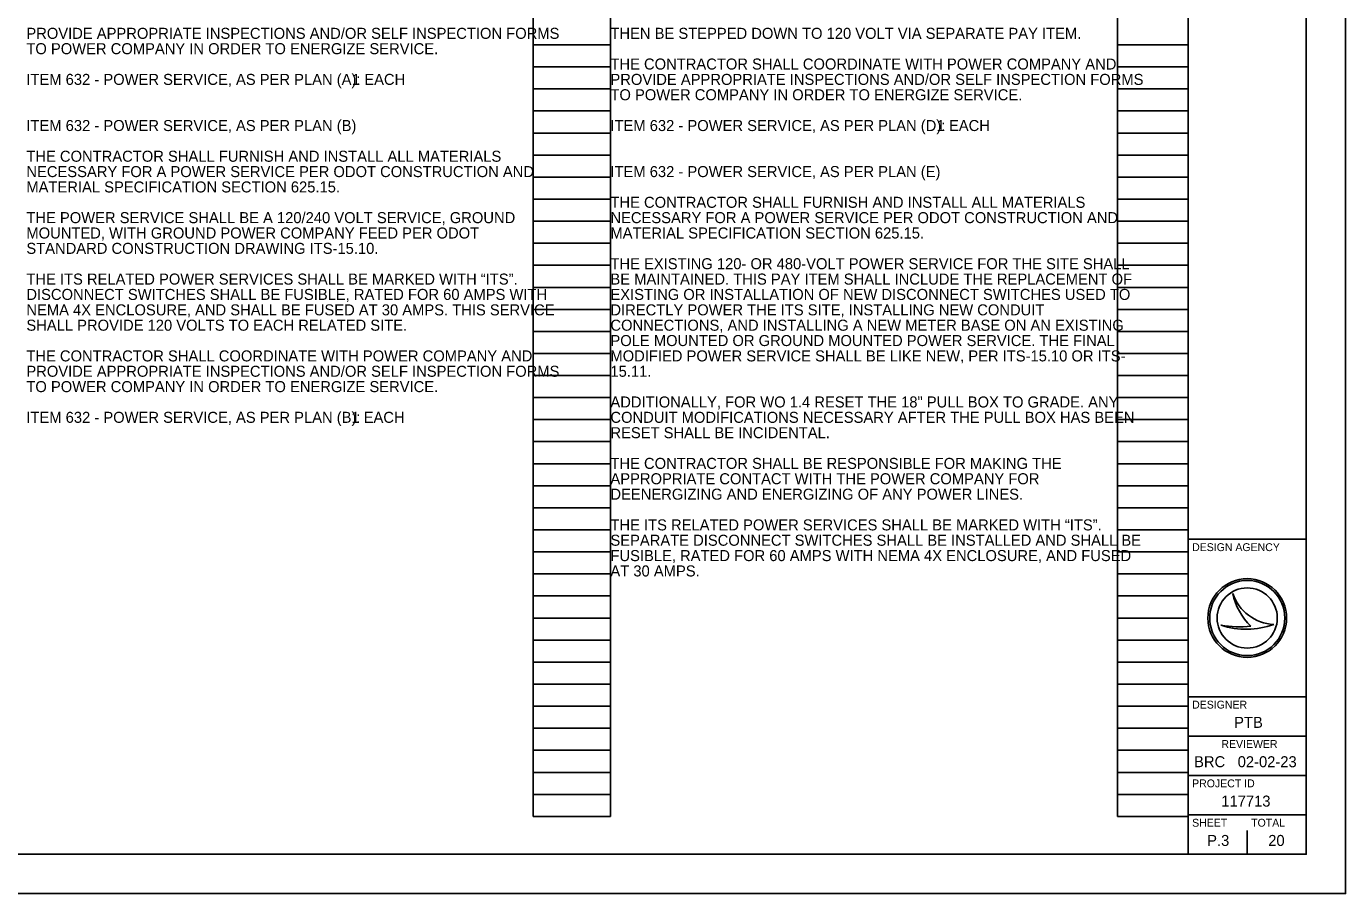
# Model space of a CAD drawing. Extents: x 0 to 34, y 0 to 22.
# Drawn here: x 17.24 to 34, y 0 to 11.01 of the extents above; entities that cross this region are included whole.
import ezdxf

# ---------------------------------------------------------------- set-up
doc = ezdxf.new("R2010")
doc.units = 0
for name, color, linetype in [('SH_Border', 7, 'Continuous'), ('SH_Cut_Line', 7, 'Continuous'), ('SH_Data', 7, 'Continuous'), ('SH_Text', 7, 'Continuous')]:
    doc.layers.add(name, color=color, linetype=linetype)

msp = doc.modelspace()

# ---------------------------------------------------------------- linework, layer by layer
at = {"layer": 'SH_Border'}
for p, q in [((32, 0.5), (32, 21.5)), ((32, 4.5), (33.5, 4.5)), ((32, 2.5), (33.5, 2.5)), ((32, 2), (33.5, 2)), ((32, 1.5), (33.5, 1.5)), ((32, 1), (33.5, 1))]:
    msp.add_line(p, q, dxfattribs=at)
msp.add_lwpolyline([(1.5, 21.5), (33.5, 21.5), (33.5, 0.5), (1.5, 0.5)], close=True, dxfattribs=at)
at = {"layer": 'SH_Cut_Line'}
msp.add_lwpolyline([(0, 0), (34, 0), (34, 22), (0, 22)], close=True, dxfattribs=at)
at = {"layer": 'SH_Data'}
for p, q in [((23.68, 0.98), (23.68, 21.14)), ((24.66, 0.98), (24.66, 21.14)), ((31.1, 0.98), (31.1, 21.14)), ((32, 0.98), (32, 21.14)), ((23.68, 10.78), (24.66, 10.78)), ((31.1, 10.78), (32, 10.78)), ((23.68, 10.5), (24.66, 10.5)), ((31.1, 10.5), (32, 10.5)), ((23.68, 10.22), (24.66, 10.22)), ((31.1, 10.22), (32, 10.22)), ((23.68, 9.94), (24.66, 9.94)), ((31.1, 9.94), (32, 9.94)), ((23.68, 9.66), (24.66, 9.66)), ((31.1, 9.66), (32, 9.66)), ((23.68, 9.38), (24.66, 9.38)), ((31.1, 9.38), (32, 9.38)), ((23.68, 9.1), (24.66, 9.1)), ((31.1, 9.1), (32, 9.1)), ((23.68, 8.82), (24.66, 8.82)), ((31.1, 8.82), (32, 8.82)), ((23.68, 8.54), (24.66, 8.54)), ((31.1, 8.54), (32, 8.54)), ((23.68, 8.26), (24.66, 8.26)), ((31.1, 8.26), (32, 8.26)), ((23.68, 7.98), (24.66, 7.98)), ((31.1, 7.98), (32, 7.98)), ((23.68, 7.7), (24.66, 7.7)), ((31.1, 7.7), (32, 7.7)), ((23.68, 7.42), (24.66, 7.42)), ((31.1, 7.42), (32, 7.42)), ((23.68, 7.14), (24.66, 7.14)), ((31.1, 7.14), (32, 7.14)), ((23.68, 6.86), (24.66, 6.86)), ((31.1, 6.86), (32, 6.86)), ((23.68, 6.58), (24.66, 6.58)), ((31.1, 6.58), (32, 6.58)), ((23.68, 6.3), (24.66, 6.3)), ((31.1, 6.3), (32, 6.3)), ((23.68, 6.02), (24.66, 6.02)), ((31.1, 6.02), (32, 6.02)), ((23.68, 5.74), (24.66, 5.74)), ((31.1, 5.74), (32, 5.74)), ((23.68, 5.46), (24.66, 5.46)), ((31.1, 5.46), (32, 5.46)), ((23.68, 5.18), (24.66, 5.18)), ((31.1, 5.18), (32, 5.18)), ((23.68, 4.9), (24.66, 4.9)), ((31.1, 4.9), (32, 4.9)), ((23.68, 4.62), (24.66, 4.62)), ((31.1, 4.62), (32, 4.62)), ((23.68, 4.34), (24.66, 4.34)), ((31.1, 4.34), (32, 4.34)), ((23.68, 4.06), (24.66, 4.06)), ((31.1, 4.06), (32, 4.06)), ((23.68, 3.78), (24.66, 3.78)), ((31.1, 3.78), (32, 3.78)), ((32.567, 3.81), (32.567, 3.81)), ((23.68, 3.5), (24.66, 3.5)), ((31.1, 3.5), (32, 3.5)), ((32.417, 3.41), (32.417, 3.41)), ((32.75, 3.5), (32.75, 3.5)), ((33.087, 3.419), (33.087, 3.419)), ((23.68, 3.22), (24.66, 3.22)), ((31.1, 3.22), (32, 3.22)), ((23.68, 2.94), (24.66, 2.94)), ((31.1, 2.94), (32, 2.94)), ((23.68, 2.66), (24.66, 2.66)), ((31.1, 2.66), (32, 2.66)), ((23.68, 2.38), (24.66, 2.38)), ((31.1, 2.38), (32, 2.38)), ((23.68, 2.1), (24.66, 2.1)), ((31.1, 2.1), (32, 2.1)), ((23.68, 1.82), (24.66, 1.82)), ((31.1, 1.82), (32, 1.82)), ((23.68, 1.54), (24.66, 1.54)), ((31.1, 1.54), (32, 1.54)), ((23.68, 1.26), (24.66, 1.26)), ((31.1, 1.26), (32, 1.26)), ((23.68, 0.98), (24.66, 0.98)), ((31.1, 0.98), (32, 0.98)), ((32.375, 0.675), (32.375, 0.675)), ((32.75, 0.5), (32.75, 0.8))]:
    msp.add_line(p, q, dxfattribs=at)
for radius in [0.5, 0.477, 0.477, 0.382]:
    msp.add_circle((32.75, 3.5), radius, dxfattribs=at)
for centre, radius, start, end in [((33.116, 3.998), 0.58, 198.9257, 198.9319), ((33.347, 3.97), 0.796, 191.6379, 191.6421), ((33.116, 3.998), 0.58, 198.9319, 267.1657), ((33.347, 3.97), 0.796, 191.6421, 226.0947), ((32.739, 4.37), 1.013, 251.4576, 290.0832), ((32.648, 4.654), 1.266, 259.4964, 259.4995), ((32.739, 4.37), 1.013, 251.4527, 251.4576), ((32.648, 4.654), 1.266, 259.4995, 276.6672)]:
    msp.add_arc(centre, radius, start, end, dxfattribs=at)

# ---------------------------------------------------------------- texts
for s, height, p in [('DESIGN AGENCY', 0.1, (32.05, 4.35)), ('DESIGNER', 0.1, (32.05, 2.35)), ('PTB', 0.14, (32.584, 2.105)), ('REVIEWER', 0.1, (32.422, 1.85)), ('BRC', 0.14, (32.075, 1.605)), ('02-02-23', 0.14, (32.629, 1.605)), ('PROJECT ID', 0.1, (32.05, 1.35)), ('117713', 0.14, (32.421, 1.105)), ('SHEET', 0.1, (32.05, 0.85)), ('TOTAL', 0.1, (32.8, 0.85)), ('P.3', 0.14, (32.241, 0.605)), ('20', 0.14, (33.017, 0.605))]:
    msp.add_text(s, height=height, dxfattribs=at).set_placement(p)
at = {"layer": 'SH_Text'}
for s, p in [('PROVIDE APPROPRIATE INSPECTIONS AND/OR SELF INSPECTION FORMS ', (17.24, 10.856)), ('THEN BE STEPPED DOWN TO 120 VOLT VIA SEPARATE PAY ITEM.', (24.66, 10.856)), ('TO POWER COMPANY IN ORDER TO ENERGIZE SERVICE.', (17.24, 10.661)), ('THE CONTRACTOR SHALL COORDINATE WITH POWER COMPANY AND ', (24.66, 10.466)), ('ITEM 632 - POWER SERVICE, AS PER PLAN (A): ', (17.24, 10.271)), ('1 EACH', (21.377, 10.271)), ('PROVIDE APPROPRIATE INSPECTIONS AND/OR SELF INSPECTION FORMS ', (24.66, 10.271)), ('TO POWER COMPANY IN ORDER TO ENERGIZE SERVICE.', (24.66, 10.076)), ('ITEM 632 - POWER SERVICE, AS PER PLAN (B)', (17.24, 9.685)), ('ITEM 632 - POWER SERVICE, AS PER PLAN (D): ', (24.66, 9.685)), ('1 EACH', (28.805, 9.685)), ('THE CONTRACTOR SHALL FURNISH AND INSTALL ALL MATERIALS ', (17.24, 9.295)), ('NECESSARY FOR A POWER SERVICE PER ODOT CONSTRUCTION AND ', (17.24, 9.1)), ('ITEM 632 - POWER SERVICE, AS PER PLAN (E)', (24.66, 9.1)), ('MATERIAL SPECIFICATION SECTION 625.15. ', (17.24, 8.905)), ('THE CONTRACTOR SHALL FURNISH AND INSTALL ALL MATERIALS ', (24.66, 8.71)), ('THE POWER SERVICE SHALL BE A 120/240 VOLT SERVICE, GROUND ', (17.24, 8.515)), ('NECESSARY FOR A POWER SERVICE PER ODOT CONSTRUCTION AND ', (24.66, 8.515)), ('MOUNTED, WITH GROUND POWER COMPANY FEED PER ODOT ', (17.24, 8.32)), ('MATERIAL SPECIFICATION SECTION 625.15. ', (24.66, 8.32)), ('STANDARD CONSTRUCTION DRAWING ITS-15.10.', (17.24, 8.125)), ('THE EXISTING 120- OR 480-VOLT POWER SERVICE FOR THE SITE SHALL ', (24.66, 7.93)), ('THE ITS RELATED POWER SERVICES SHALL BE MARKED WITH “ITS”. ', (17.24, 7.735)), ('BE MAINTAINED. THIS PAY ITEM SHALL INCLUDE THE REPLACEMENT OF ', (24.66, 7.735)), ('DISCONNECT SWITCHES SHALL BE FUSIBLE, RATED FOR 60 AMPS WITH ', (17.24, 7.54)), ('EXISTING OR INSTALLATION OF NEW DISCONNECT SWITCHES USED TO ', (24.66, 7.54)), ('NEMA 4X ENCLOSURE, AND SHALL BE FUSED AT 30 AMPS. THIS SERVICE ', (17.24, 7.344)), ('DIRECTLY POWER THE ITS SITE, INSTALLING NEW CONDUIT ', (24.66, 7.344)), ('SHALL PROVIDE 120 VOLTS TO EACH RELATED SITE.', (17.24, 7.149)), ('CONNECTIONS, AND INSTALLING A NEW METER BASE ON AN EXISTING ', (24.66, 7.149)), ('POLE MOUNTED OR GROUND MOUNTED POWER SERVICE. THE FINAL ', (24.66, 6.954)), ('THE CONTRACTOR SHALL COORDINATE WITH POWER COMPANY AND ', (17.24, 6.759)), ('MODIFIED POWER SERVICE SHALL BE LIKE NEW, PER ITS-15.10 OR ITS-', (24.66, 6.759)), ('PROVIDE APPROPRIATE INSPECTIONS AND/OR SELF INSPECTION FORMS ', (17.24, 6.564)), ('15.11.', (24.66, 6.564)), ('TO POWER COMPANY IN ORDER TO ENERGIZE SERVICE.', (17.24, 6.369)), ('ADDITIONALLY, FOR WO 1.4 RESET THE 18" PULL BOX TO GRADE. ANY ', (24.66, 6.174)), ('ITEM 632 - POWER SERVICE, AS PER PLAN (B): ', (17.24, 5.979)), ('1 EACH', (21.369, 5.979)), ('CONDUIT MODIFICATIONS NECESSARY AFTER THE PULL BOX HAS BEEN ', (24.66, 5.979)), ('RESET SHALL BE INCIDENTAL. ', (24.66, 5.784)), ('THE CONTRACTOR SHALL BE RESPONSIBLE FOR MAKING THE ', (24.66, 5.394)), ('APPROPRIATE CONTACT WITH THE POWER COMPANY FOR ', (24.66, 5.199)), ('DEENERGIZING AND ENERGIZING OF ANY POWER LINES.', (24.66, 5.003)), ('THE ITS RELATED POWER SERVICES SHALL BE MARKED WITH “ITS”. ', (24.66, 4.613)), ('SEPARATE DISCONNECT SWITCHES SHALL BE INSTALLED AND SHALL BE ', (24.66, 4.418)), ('FUSIBLE, RATED FOR 60 AMPS WITH NEMA 4X ENCLOSURE, AND FUSED ', (24.66, 4.223)), ('AT 30 AMPS.', (24.66, 4.028))]:
    msp.add_text(s, height=0.14, dxfattribs=at).set_placement(p)

doc.saveas('drawing.dxf')
